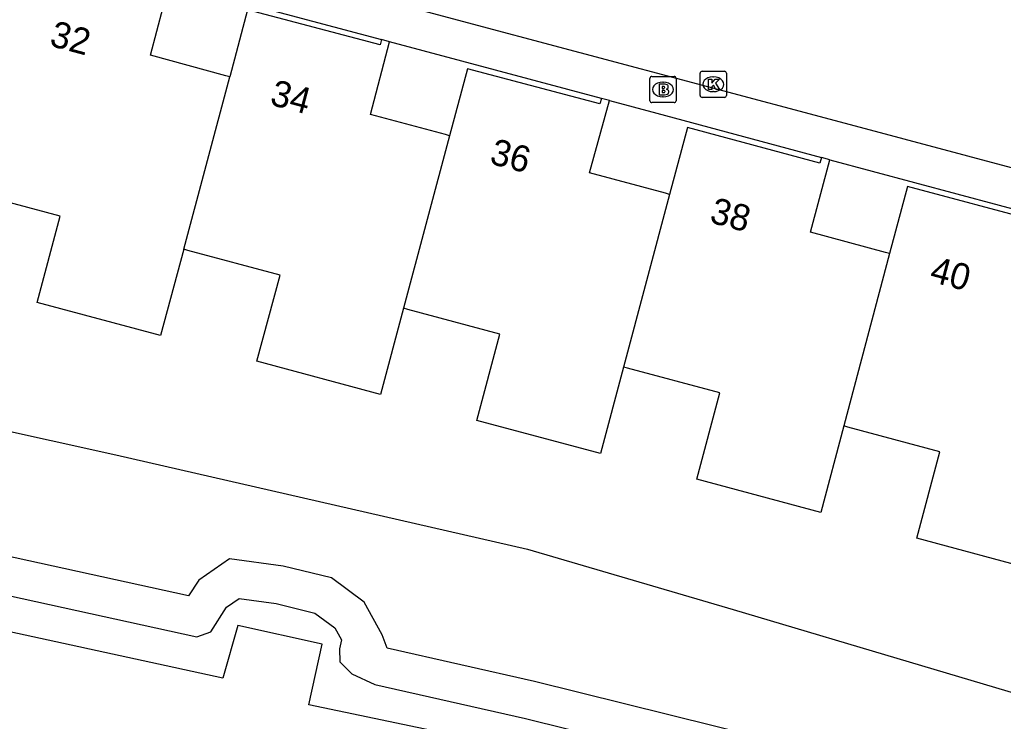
# Model space of a CAD drawing. Extents: x 162990 to 165007, y 383433 to 384336.
# Drawn here: x 163585.79 to 163623.33, y 383919.55 to 383946.33 of the extents above; entities that cross this region are included whole.
import ezdxf

# ---------------------------------------------------------------- set-up
doc = ezdxf.new("R2010")
doc.units = 0
for name, color, linetype in [('IMGEO_Brandkraan', 7, 'Continuous'), ('IMGEO_Geluidsscherm', 7, 'Continuous'), ('IMGEO_Grasland_overig', 7, 'Continuous'), ('IMGEO_Kolk', 7, 'Continuous'), ('IMGEO_Pand', 7, 'Continuous'), ('IMGEO_Pand_nummerreeks', 7, 'Continuous'), ('IMGEO_Rijbaan_lokaal_open', 7, 'Continuous'), ('IMGEO_Spoorbaan_halfverhard', 7, 'Continuous'), ('IMGEO_Voetpad_open', 7, 'Continuous')]:
    doc.layers.add(name, color=color, linetype=linetype)

msp = doc.modelspace()

# ---------------------------------------------------------------- linework, layer by layer
at = {"layer": 'IMGEO_Brandkraan'}
for p, q in [((163609.844, 383943.241), (163609.844, 383944.093)), ((163609.919, 383944.167), (163610.771, 383944.167)), ((163610.845, 383944.093), (163610.845, 383943.241)), ((163610.332, 383943.947), (163610.357, 383943.947)), ((163610.355, 383943.387), (163610.33, 383943.387)), ((163610.771, 383943.167), (163609.919, 383943.167))]:
    msp.add_line(p, q, dxfattribs=at)
for points in [[(163609.844, 383943.241), (163609.844, 383944.093)], [(163609.919, 383944.167), (163610.771, 383944.167)], [(163610.845, 383944.093), (163610.845, 383943.241)], [(163610.192, 383943.867), (163610.192, 383943.467), (163610.405, 383943.467)], [(163610.423, 383943.867), (163610.192, 383943.867)], [(163610.371, 383943.786), (163610.317, 383943.786), (163610.317, 383943.71)], [(163610.317, 383943.71), (163610.37, 383943.71)], [(163610.379, 383943.634), (163610.317, 383943.634), (163610.317, 383943.553)], [(163610.317, 383943.553), (163610.379, 383943.553)], [(163610.771, 383943.167), (163609.919, 383943.167)]]:
    msp.add_lwpolyline(points, dxfattribs=at)
for centre, radius, start, end in [((163609.921, 383944.091), 0.0765, 91.552, 178.448), ((163609.921, 383944.091), 0.0765, 91.552, 178.448), ((163610.769, 383944.091), 0.0765, 1.552, 88.448), ((163610.769, 383944.091), 0.0765, 1.552, 88.448), ((163610.372, 383943.748), 0.0379, 267.8285, 90.9355), ((163610.38, 383943.593), 0.0404, 269.8759, 90.5077), ((163610.427, 383943.722), 0.145, 59.4692, 91.5367), ((163610.452, 383943.769), 0.0922, 285.5137, 58.1501), ((163610.457, 383943.577), 0.105, 301.3115, 78.989), ((163609.921, 383943.243), 0.0765, 181.552, 268.448), ((163609.921, 383943.243), 0.0765, 181.552, 268.448), ((163610.411, 383943.718), 0.251, 268.6676, 293.5347), ((163610.769, 383943.243), 0.0765, 271.552, 358.448), ((163610.769, 383943.243), 0.0765, 271.552, 358.448)]:
    msp.add_arc(centre, radius, start, end, dxfattribs=at)
for centre, major_axis, ratio, start_param, end_param in [((163610.331, 383943.667), (-0.387, 0.002), 0.722429, 4.712389, 7.853982), ((163610.356, 383943.667), (-0.39, 0.002), 0.717154, 1.570796, 4.712389)]:
    msp.add_ellipse(centre, major_axis=major_axis, ratio=ratio, start_param=start_param, end_param=end_param, dxfattribs=at)
at = {"layer": 'IMGEO_Geluidsscherm'}
msp.add_lwpolyline([(163555.79, 383937.222), (163564.646, 383935.431), (163579.692, 383931.881), (163589.465, 383929.727), (163599.072, 383927.517), (163605.168, 383926.118), (163613.02, 383923.823), (163634.587, 383917.404), (163655.721, 383911.082), (163672.29, 383906.041), (163680.003, 383903.652), (163680.457, 383903.531)], dxfattribs=at)
at = {"layer": 'IMGEO_Grasland_overig'}
for points in [[(163443.216, 383956.832), (163466.917, 383952.997), (163487.883, 383949.526), (163505.529, 383947.116), (163506.203, 383946.946), (163536.04, 383941.212), (163554.665, 383937.466), (163555.79, 383937.222), (163564.646, 383935.431), (163579.692, 383931.881), (163589.465, 383929.727), (163599.072, 383927.517), (163605.168, 383926.118), (163613.02, 383923.823), (163634.587, 383917.404), (163655.721, 383911.082), (163672.29, 383906.041), (163680.003, 383903.652)], [(163622.617, 383916.804), (163605.433, 383921.076), (163599.814, 383922.344), (163599.628, 383922.854), (163598.941, 383924.094), (163597.689, 383925.023), (163595.853, 383925.477), (163593.798, 383925.758), (163592.628, 383924.943), (163592.233, 383924.338), (163579.508, 383927.127), (163551.99, 383932.912), (163540.41, 383935.479)], [(163569.312, 383927.786), (163579.204, 383925.707), (163592.552, 383922.776), (163593.084, 383922.969), (163593.689, 383923.912), (163594.163, 383924.242), (163595.58, 383924.048), (163597.058, 383923.683), (163597.824, 383923.115), (163598.078, 383922.656), (163597.991, 383922.317), (163598.005, 383921.824), (163598.469, 383921.362), (163599.348, 383920.961), (163605.098, 383919.663), (163622.278, 383915.391)]]:
    msp.add_lwpolyline(points, dxfattribs=at)
at = {"layer": 'IMGEO_Kolk'}
for p, q in [((163611.835, 383944.366), (163612.687, 383944.366)), ((163611.76, 383943.44), (163611.76, 383944.292)), ((163612.248, 383944.146), (163612.273, 383944.146)), ((163612.761, 383944.292), (163612.761, 383943.44)), ((163612.271, 383943.586), (163612.246, 383943.586)), ((163612.687, 383943.366), (163611.835, 383943.366))]:
    msp.add_line(p, q, dxfattribs=at)
for points in [[(163611.835, 383944.366), (163612.687, 383944.366)], [(163611.76, 383943.44), (163611.76, 383944.292)], [(163612.081, 383944.066), (163612.204, 383944.066), (163612.204, 383943.915), (163612.334, 383944.066), (163612.498, 383944.066), (163612.352, 383943.915), (163612.505, 383943.666), (163612.353, 383943.666), (163612.268, 383943.83), (163612.204, 383943.763), (163612.204, 383943.666), (163612.081, 383943.666), (163612.081, 383944.066)], [(163612.761, 383944.292), (163612.761, 383943.44)], [(163612.687, 383943.366), (163611.835, 383943.366)]]:
    msp.add_lwpolyline(points, dxfattribs=at)
for centre, start, end in [((163611.837, 383944.29), 91.552, 178.448), ((163611.837, 383944.29), 91.552, 178.448), ((163612.685, 383944.29), 1.552, 88.448), ((163612.685, 383944.29), 1.552, 88.448), ((163611.837, 383943.442), 181.552, 268.448), ((163611.837, 383943.442), 181.552, 268.448), ((163612.685, 383943.442), 271.552, 358.448), ((163612.685, 383943.442), 271.552, 358.448)]:
    msp.add_arc(centre, 0.0765, start, end, dxfattribs=at)
for centre, major_axis, ratio, start_param, end_param in [((163612.247, 383943.866), (-0.387, 0.002), 0.722429, 4.712389, 7.853982), ((163612.272, 383943.866), (-0.39, 0.002), 0.717154, 1.570796, 4.712389)]:
    msp.add_ellipse(centre, major_axis=major_axis, ratio=ratio, start_param=start_param, end_param=end_param, dxfattribs=at)
at = {"layer": 'IMGEO_Pand'}
for points in [[(163593.811, 383944.153), (163593.661, 383944.193), (163590.784, 383944.972), (163591.513, 383947.737)], [(163599.6, 383945.572), (163599.543, 383945.366), (163594.491, 383946.704), (163593.811, 383944.153)], [(163602.195, 383941.903), (163602.04, 383941.945), (163599.175, 383942.711), (163599.908, 383945.487)], [(163599.908, 383945.487), (163599.6, 383945.572)], [(163607.992, 383943.329), (163607.931, 383943.114), (163602.877, 383944.458), (163602.195, 383941.903)], [(163592.052, 383937.567), (163593.811, 383944.153)], [(163610.597, 383939.663), (163610.436, 383939.707), (163607.535, 383940.488), (163608.296, 383943.245)], [(163608.296, 383943.245), (163607.992, 383943.329)], [(163616.395, 383941.068), (163616.331, 383940.858), (163611.276, 383942.214), (163610.597, 383939.663)], [(163602.195, 383941.903), (163600.439, 383935.318)], [(163618.992, 383937.409), (163618.835, 383937.451), (163615.972, 383938.221), (163616.704, 383940.986)], [(163616.704, 383940.986), (163616.395, 383941.068)], [(163624.788, 383938.825), (163624.72, 383938.612), (163619.67, 383939.96), (163618.992, 383937.409)], [(163592.052, 383937.567), (163591.172, 383934.273), (163586.456, 383935.537), (163587.339, 383938.83), (163583.817, 383939.773), (163583.662, 383939.815)], [(163610.597, 383939.663), (163608.836, 383933.068)], [(163600.439, 383935.318), (163599.561, 383932.024), (163594.846, 383933.293), (163595.733, 383936.586), (163592.21, 383937.525), (163592.052, 383937.567)], [(163618.992, 383937.409), (163617.242, 383930.824)], [(163608.836, 383933.068), (163607.957, 383929.773), (163603.237, 383931.035), (163604.118, 383934.329), (163600.601, 383935.274), (163600.439, 383935.318)], [(163617.242, 383930.824), (163616.366, 383927.527), (163611.629, 383928.789), (163612.506, 383932.084), (163608.993, 383933.026), (163608.836, 383933.068)], [(163625.624, 383928.567), (163624.746, 383925.272), (163620.03, 383926.538), (163620.914, 383929.831), (163617.398, 383930.782), (163617.242, 383930.824)]]:
    msp.add_lwpolyline(points, dxfattribs=at)
at = {"layer": 'IMGEO_Rijbaan_lokaal_open'}
msp.add_lwpolyline([(163650.042, 383933.629), (163616.922, 383942.467), (163602.315, 383946.365), (163591.682, 383949.215)], dxfattribs=at)
at = {"layer": 'IMGEO_Spoorbaan_halfverhard'}
msp.add_lwpolyline([(163679.08, 383900.453), (163670.387, 383902.701), (163634.665, 383911.508), (163602.361, 383919.022), (163596.824, 383920.182), (163597.332, 383922.493), (163594.114, 383923.205), (163593.547, 383921.194), (163569.036, 383926.529)], dxfattribs=at)
at = {"layer": 'IMGEO_Voetpad_open'}
for points in [[(163591.513, 383947.737), (163599.6, 383945.572)], [(163607.992, 383943.329), (163599.908, 383945.487)], [(163608.296, 383943.245), (163610.107, 383942.758), (163616.395, 383941.068)], [(163616.704, 383940.986), (163624.788, 383938.825)]]:
    msp.add_lwpolyline(points, dxfattribs=at)

# ---------------------------------------------------------------- texts
at = {"layer": 'IMGEO_Pand_nummerreeks'}
for s, rotation, p in [('32', 345.0343, (163586.891, 383945.346)), ('34', 345.1661, (163595.301, 383943.097)), ('36', 345.1088, (163603.686, 383940.849)), ('38', 344.977, (163612.081, 383938.602)), ('40', 345.0573, (163620.477, 383936.35))]:
    msp.add_text(s, height=1, rotation=rotation, dxfattribs=at).set_placement(p)

doc.saveas('drawing.dxf')
